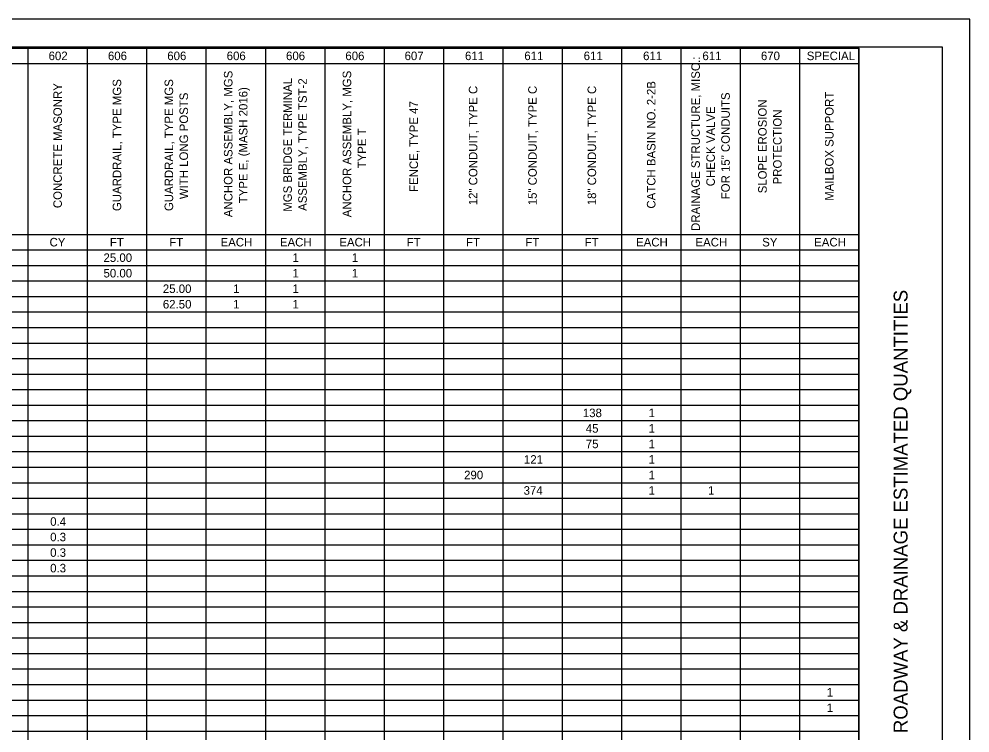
# Model space of a CAD drawing. Extents: x 0 to 34, y 0 to 22.
# Drawn here: x 16.87 to 34, y 9.13 to 22 of the extents above; entities that cross this region are included whole.
import ezdxf

# ---------------------------------------------------------------- set-up
doc = ezdxf.new("R2010")
doc.units = 0
for name, color, linetype in [('SH_Border', 7, 'Continuous'), ('SH_Cut_Line', 7, 'Continuous'), ('SH_Data', 7, 'Continuous'), ('SH_Text', 7, 'Continuous')]:
    doc.layers.add(name, color=color, linetype=linetype)

msp = doc.modelspace()

# ---------------------------------------------------------------- linework, layer by layer
at = {"layer": 'SH_Border'}
msp.add_line((32, 0.5), (32, 21.5), dxfattribs=at)
msp.add_lwpolyline([(1.5, 21.5), (33.5, 21.5), (33.5, 0.5), (1.5, 0.5)], close=True, dxfattribs=at)
at = {"layer": 'SH_Cut_Line'}
msp.add_lwpolyline([(0, 0), (34, 0), (34, 22), (0, 22)], close=True, dxfattribs=at)
at = {"layer": 'SH_Data'}
for p, q in [((1.483, 21.475), (32, 21.475)), ((17.029, 21.475), (17.029, 0.5)), ((18.099, 21.475), (18.099, 0.5)), ((19.168, 21.475), (19.168, 0.5)), ((20.237, 21.475), (20.237, 0.5)), ((21.307, 21.475), (21.307, 0.5)), ((22.376, 21.475), (22.376, 0.5)), ((23.445, 21.475), (23.445, 0.5)), ((24.515, 21.475), (24.515, 0.5)), ((25.584, 21.475), (25.584, 0.5)), ((26.653, 21.475), (26.653, 0.5)), ((27.723, 21.475), (27.723, 0.5)), ((28.792, 21.475), (28.792, 0.5)), ((29.861, 21.475), (29.861, 0.5)), ((30.931, 21.475), (30.931, 0.5)), ((32, 21.475), (32, 0.5)), ((9.544, 21.196), (32, 21.196)), ((9.544, 18.119), (32, 18.119)), ((1.483, 17.84), (32, 17.84)), ((1.483, 17.56), (32, 17.56)), ((1.483, 17.28), (32, 17.28)), ((1.483, 17.001), (32, 17.001)), ((1.483, 16.721), (32, 16.721)), ((1.483, 16.441), (32, 16.441)), ((1.483, 16.162), (32, 16.162)), ((1.483, 15.882), (32, 15.882)), ((1.483, 15.602), (32, 15.602)), ((1.483, 15.323), (32, 15.323)), ((1.483, 15.043), (32, 15.043)), ((1.483, 14.763), (32, 14.763)), ((1.483, 14.484), (32, 14.484)), ((1.483, 14.204), (32, 14.204)), ((1.483, 13.924), (32, 13.924)), ((1.483, 13.644), (32, 13.644)), ((1.483, 13.365), (32, 13.365)), ((1.483, 13.085), (32, 13.085)), ((1.483, 12.805), (32, 12.805)), ((1.483, 12.526), (32, 12.526)), ((1.483, 12.246), (32, 12.246)), ((1.483, 11.966), (32, 11.966)), ((1.483, 11.687), (32, 11.687)), ((1.483, 11.407), (32, 11.407)), ((1.483, 11.127), (32, 11.127)), ((1.483, 10.848), (32, 10.848)), ((1.483, 10.568), (32, 10.568)), ((1.483, 10.288), (32, 10.288)), ((1.483, 10.009), (32, 10.009)), ((1.483, 9.729), (32, 9.729)), ((1.483, 9.449), (32, 9.449)), ((1.483, 9.17), (32, 9.17))]:
    msp.add_line(p, q, dxfattribs=at)

# ---------------------------------------------------------------- texts
msp.add_text('ROADWAY & DRAINAGE ESTIMATED QUANTITIES', height=0.25, rotation=90, dxfattribs=at).set_placement((32.875, 9.133))
at = {"layer": 'SH_Text'}
for s, height, p in [('602', 0.1538, (17.402, 21.259)), ('606', 0.1538, (18.471, 21.259)), ('606', 0.1538, (19.54, 21.259)), ('606', 0.1538, (20.61, 21.259)), ('606', 0.1538, (21.679, 21.259)), ('606', 0.1538, (22.748, 21.259)), ('607', 0.1538, (23.815, 21.259)), ('611', 0.1538, (24.903, 21.259)), ('611', 0.1538, (25.972, 21.259)), ('611', 0.1538, (27.041, 21.259)), ('611', 0.1538, (28.111, 21.259)), ('611', 0.1538, (29.18, 21.259)), ('670', 0.1538, (30.234, 21.259)), ('SPECIAL', 0.1538, (31.06, 21.259)), ('CY', 0.1538, (17.419, 17.902)), ('FT', 0.1538, (18.506, 17.902)), ('FT', 0.1538, (19.575, 17.902)), ('EACH', 0.1538, (20.5, 17.902)), ('EACH', 0.1538, (21.569, 17.902)), ('EACH', 0.1538, (22.639, 17.902)), ('FT', 0.1538, (23.852, 17.902)), ('FT', 0.1538, (24.922, 17.902)), ('FT', 0.1538, (25.991, 17.902)), ('FT', 0.1538, (27.06, 17.902)), ('EACH', 0.1538, (27.985, 17.902)), ('EACH', 0.1538, (29.055, 17.902)), ('SY', 0.1538, (30.257, 17.902)), ('EACH', 0.1538, (31.193, 17.902)), ('25.00', 0.1538, (18.391, 17.623)), ('1', 0.154, (21.795, 17.623)), ('1', 0.154, (22.864, 17.623)), ('50.00', 0.1538, (18.391, 17.343)), ('1', 0.154, (21.795, 17.343)), ('1', 0.154, (22.864, 17.343)), ('25.00', 0.1538, (19.46, 17.063)), ('1', 0.154, (20.726, 17.063)), ('1', 0.154, (21.795, 17.063)), ('62.50', 0.1538, (19.46, 16.784)), ('1', 0.154, (20.726, 16.784)), ('1', 0.154, (21.795, 16.784)), ('138', 0.1538, (27.026, 14.826)), ('1', 0.154, (28.211, 14.826)), ('45', 0.1538, (27.079, 14.546)), ('1', 0.154, (28.211, 14.546)), ('75', 0.1538, (27.079, 14.267)), ('1', 0.154, (28.211, 14.267)), ('121', 0.1538, (25.965, 13.987)), ('1', 0.154, (28.211, 13.987)), ('290', 0.1538, (24.887, 13.707)), ('1', 0.154, (28.211, 13.707)), ('374', 0.1538, (25.959, 13.428)), ('1', 0.154, (28.211, 13.428)), ('1', 0.154, (29.28, 13.428)), ('0.4', 0.1538, (17.431, 12.868)), ('0.3', 0.1538, (17.43, 12.589)), ('0.3', 0.1538, (17.43, 12.309)), ('0.3', 0.1538, (17.43, 12.029)), ('1', 0.154, (31.419, 9.792)), ('1', 0.154, (31.419, 9.512))]:
    msp.add_text(s, height=height, dxfattribs=at).set_placement(p)
for s, height, p in [('DRAINAGE STRUCTURE, MISC.: ', 0.15382, (29.134, 18.181)), ('GUARDRAIL, TYPE MGS', 0.15382, (18.71, 18.539)), ('GUARDRAIL, TYPE MGS', 0.15382, (19.645, 18.539)), ('ANCHOR ASSEMBLY, MGS ', 0.15382, (20.714, 18.428)), ('MGS BRIDGE TERMINAL ', 0.15382, (21.784, 18.527)), ('ASSEMBLY, TYPE TST-2', 0.15382, (22.053, 18.542)), ('ANCHOR ASSEMBLY, MGS ', 0.15382, (22.853, 18.428)), ('CONCRETE MASONRY', 0.15382, (17.641, 18.592)), ('TYPE E, (MASH 2016)', 0.15382, (20.984, 18.68)), ('12" CONDUIT, TYPE C', 0.15382, (25.126, 18.644)), ('15" CONDUIT, TYPE C', 0.15382, (26.196, 18.644)), ('18" CONDUIT, TYPE C', 0.15382, (27.265, 18.644)), ('CATCH BASIN NO. 2-2B', 0.15382, (28.334, 18.584)), ('WITH LONG POSTS', 0.15382, (19.914, 18.754)), ('FOR 15" CONDUITS', 0.15382, (29.673, 18.752)), ('MAILBOX SUPPORT', 0.15382, (31.542, 18.725)), ('FENCE, TYPE 47', 0.15382, (24.057, 18.885)), ('CHECK VALVE', 0.15382, (29.404, 18.986)), ('SLOPE EROSION', 0.15382, (30.338, 18.859)), ('PROTECTION', 0.1538, (30.608, 19.02)), ('TYPE T', 0.1538, (23.122, 19.309))]:
    msp.add_text(s, height=height, rotation=90, dxfattribs=at).set_placement(p)

doc.saveas('drawing.dxf')
